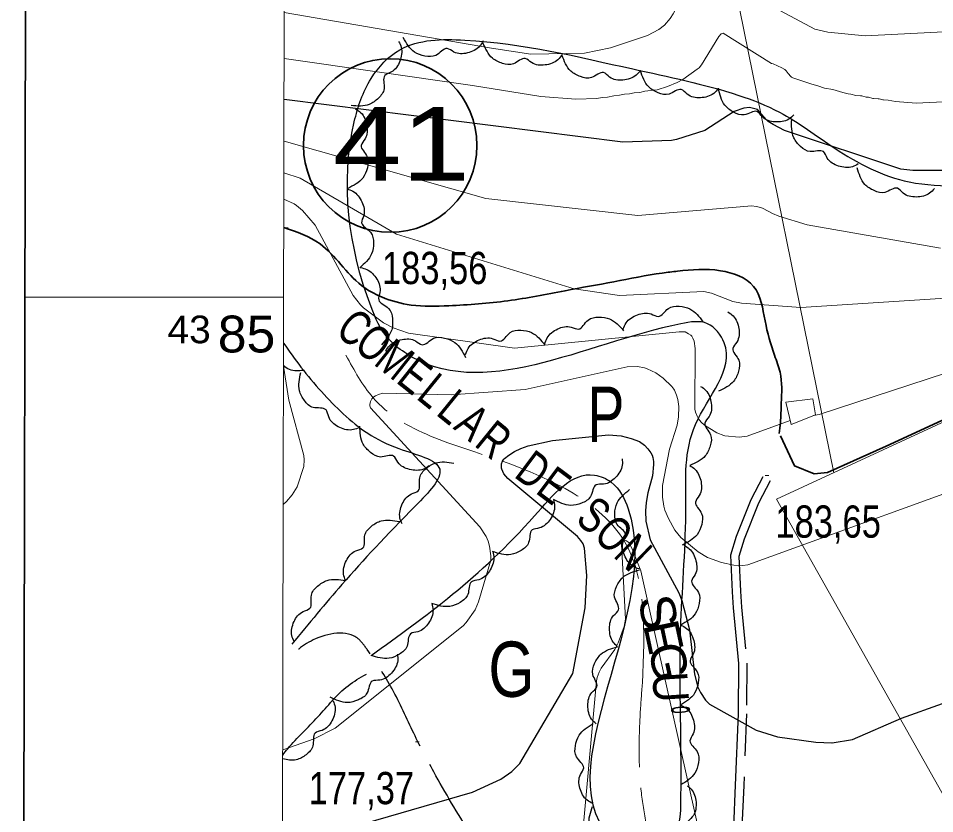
# Model space of a CAD drawing. Extents: x 483847 to 488453, y 4383581 to 4386795.
# Drawn here: x 484030.4 to 484279, y 4384859.8 to 4385075.7 of the extents above; entities that cross this region are included whole.
import ezdxf
from ezdxf.enums import TextEntityAlignment as Align

# ---------------------------------------------------------------- set-up
doc = ezdxf.new("R2010")
doc.units = 0
doc.header["$LTSCALE"] = 3.8
for name, pattern in [('DOTTED', [1.5, 0.3, -1.2]), ('LONG_DASHED', [7.5, 6, -1.5]), ('MEDIUM_DASHED', [4.5, 3, -1.5])]:
    doc.linetypes.add(name, pattern=pattern)
for name, color, linetype, lineweight in [('1', 7, 'Continuous', 13), ('13', 7, 'Continuous', 25), ('15', 7, 'LONG_DASHED', 13), ('2', 7, 'DOTTED', 13), ('27', 7, 'Continuous', 25), ('38', 7, 'Continuous', 25), ('47', 7, 'Continuous', 35), ('51', 7, 'Continuous', 13), ('6', 7, 'Continuous', 35), ('7', 7, 'Continuous', 13), ('8', 7, 'Continuous', 25), ('9', 7, 'Continuous', 13)]:
    doc.layers.add(name, color=color, linetype=linetype, lineweight=lineweight)
doc.layers.add('31', color=7, linetype='Continuous')
doc.layers.add('5', color=7, linetype='Continuous')

msp = doc.modelspace()

# ---------------------------------------------------------------- linework, layer by layer
at = {"layer": '1'}
msp.add_line((484102.37, 4385000), (484032.14, 4385000), dxfattribs=at)
at = {"layer": '1', "lineweight": 35}
msp.add_lwpolyline([(484035.03, 4386519.58), (487752.53, 4386512.52), (487747.86, 4384057.52), (484030.36, 4384064.59)], close=True, dxfattribs=at)
at = {"layer": '1'}
msp.add_lwpolyline([(484105.5, 4386448.1), (487681.9, 4386441.2), (487678, 4384129), (484100.5, 4384135.8)], close=True, dxfattribs=at)
at = {"layer": '15'}
for points in [[(484199.72, 4384895.26), (484194.73, 4384933.86), (484161.74, 4384955.47), (484126.6, 4384972.74), (484119.28, 4384984.24)], [(484199.72, 4384895.26), (484199.12, 4384887.01), (484198.9, 4384873.03), (484199.36, 4384866), (484200.74, 4384856.93), (484201.27, 4384852.68), (484201.35, 4384844.63)]]:
    msp.add_spline(points, degree=3, dxfattribs=at)
at = {"layer": '27'}
for points in [[(484126.09, 4384902.79), (484170.42, 4384940.62), (484186.72, 4384951.71), (484191.28, 4384949.75), (484195.85, 4384942.58), (484195.2, 4384850.61), (484198.46, 4384849.31), (484203.02, 4384849.96), (484206.93, 4384851.91), (484210.19, 4384864.31), (484210.19, 4384911.92), (484211.5, 4384943.23), (484214.1, 4384965.41), (484221.93, 4384987.58), (484217.36, 4384992.8), (484210.19, 4384992.8), (484135.22, 4384984.97), (484130.65, 4384988.89), (484126.09, 4384997.37), (484121.53, 4385047.59), (484126.09, 4385059.33), (484133.91, 4385067.16), (484151.52, 4385069.77), (484197.15, 4385061.94), (484225.84, 4385054.77), (484236.92, 4385050.2), (484251.92, 4385040.42), (484272.13, 4385031.28), (484285.82, 4385029.98), (484298.2, 4385029.33), (484332.11, 4385039.76), (484352.32, 4385052.16), (484358.18, 4385050.2), (484379.05, 4385045.63), (484396, 4385044.98), (484413.6, 4385057.38), (484413.6, 4385076.29), (484415.56, 4385110.21), (484421.42, 4385117.38), (484434.46, 4385125.86), (484452.06, 4385127.17), (484517.26, 4385131.08), (484535.51, 4385145.43), (484539.43, 4385153.26), (484534.21, 4385163.04), (484527.69, 4385172.17), (484530.3, 4385183.26), (484560.29, 4385234.79), (484583.76, 4385251.75), (484588.32, 4385252.4), (484664.6, 4385247.83), (484699.15, 4385252.4), (484722.1, 4385262.06)], [(484133.56, 4385069.43), (484134.25, 4385067.79), (484133.87, 4385064.02), (484131.59, 4385061.12), (484129.79, 4385060.14), (484129.61, 4385056.59), (484128.08, 4385054.02), (484125.6, 4385052.3), (484120.65, 4385051.99)], [(484156.51, 4385069.57), (484155.55, 4385068.08), (484152.22, 4385066.27), (484148.54, 4385066.53), (484146.71, 4385067.47), (484143.68, 4385065.62), (484140.7, 4385065.44), (484137.88, 4385066.53), (484134.83, 4385070.44)], [(484177.91, 4385065.83), (484176.8, 4385064.45), (484173.29, 4385063.01), (484169.65, 4385063.66), (484167.94, 4385064.8), (484164.72, 4385063.29), (484161.74, 4385063.43), (484159.06, 4385064.82), (484156.45, 4385069.04)], [(484199.18, 4385061.55), (484198.01, 4385060.22), (484194.44, 4385058.93), (484190.83, 4385059.74), (484189.17, 4385060.95), (484185.89, 4385059.58), (484182.92, 4385059.85), (484180.3, 4385061.36), (484177.88, 4385065.69)], [(484220.29, 4385056.57), (484219.07, 4385055.29), (484215.46, 4385054.13), (484211.89, 4385055.07), (484210.27, 4385056.34), (484206.94, 4385055.09), (484203.98, 4385055.47), (484201.42, 4385057.07), (484199.16, 4385061.48)], [(484240.79, 4385049.44), (484239.43, 4385048.3), (484235.7, 4385047.57), (484232.27, 4385048.91), (484230.81, 4385050.35), (484227.36, 4385049.49), (484224.46, 4385050.21), (484222.09, 4385052.09), (484220.35, 4385056.74)], [(484121.88, 4385051.1), (484123.31, 4385050.06), (484124.92, 4385046.63), (484124.45, 4385042.96), (484123.4, 4385041.2), (484125.07, 4385038.06), (484125.08, 4385035.07), (484123.83, 4385032.32), (484119.74, 4385029.51)], [(484258.29, 4385036.18), (484256.7, 4385035.4), (484252.91, 4385035.59), (484249.9, 4385037.73), (484248.83, 4385039.49), (484245.27, 4385039.49), (484242.64, 4385040.88), (484240.8, 4385043.28), (484240.23, 4385048.21)], [(484278.94, 4385029.45), (484277.67, 4385028.2), (484274.02, 4385027.18), (484270.48, 4385028.24), (484268.91, 4385029.57), (484265.54, 4385028.44), (484262.6, 4385028.92), (484260.09, 4385030.61), (484257.99, 4385035.1)], [(484119.5, 4385029.37), (484121.16, 4385028.73), (484123.6, 4385025.83), (484124.09, 4385022.17), (484123.53, 4385020.2), (484125.96, 4385017.6), (484126.74, 4385014.71), (484126.23, 4385011.73), (484123.01, 4385007.96)], [(484123.21, 4385008.01), (484124.92, 4385007.54), (484127.64, 4385004.9), (484128.5, 4385001.31), (484128.15, 4384999.29), (484130.82, 4384996.95), (484131.89, 4384994.16), (484131.69, 4384991.14), (484128.87, 4384987.06)], [(484194.54, 4384991.39), (484195.3, 4384993), (484198.37, 4384995.22), (484202.06, 4384995.44), (484203.99, 4384994.74), (484206.76, 4384996.97), (484209.69, 4384997.53), (484212.63, 4384996.81), (484216.15, 4384993.33)], [(484173.22, 4384987.26), (484173.85, 4384988.92), (484176.74, 4384991.38), (484180.4, 4384991.89), (484182.38, 4384991.34), (484184.96, 4384993.78), (484187.84, 4384994.58), (484190.83, 4384994.09), (484194.62, 4384990.89)], [(484222.93, 4384996.02), (484224.34, 4384994.94), (484225.88, 4384991.48), (484225.34, 4384987.83), (484224.26, 4384986.08), (484225.87, 4384982.91), (484225.82, 4384979.93), (484224.51, 4384977.2), (484220.37, 4384974.47)], [(484151.72, 4384984.48), (484152.43, 4384986.1), (484155.45, 4384988.41), (484159.13, 4384988.72), (484161.07, 4384988.07), (484163.79, 4384990.37), (484166.7, 4384991.01), (484169.66, 4384990.37), (484173.27, 4384986.97)], [(484102.34, 4384987.5), (484107.05, 4384981.01), (484118.55, 4384968.34), (484133.64, 4384958.91), (484144.7, 4384953.31), (484138.24, 4384943.46), (484118.16, 4384922.01), (484104.59, 4384905.83)], [(484130.07, 4384985.37), (484131.09, 4384986.83), (484134.49, 4384988.51), (484138.16, 4384988.11), (484139.94, 4384987.1), (484143.05, 4384988.83), (484146.03, 4384988.9), (484148.81, 4384987.7), (484151.7, 4384983.67)], [(484107.65, 4384980.14), (484105.89, 4384979.98), (484102.4, 4384981.48), (484102.33, 4384981.59)], [(484122.57, 4384964.44), (484120.85, 4384963.97), (484117.16, 4384964.85), (484114.59, 4384967.5), (484113.87, 4384969.42), (484110.37, 4384970.07), (484108.03, 4384971.92), (484106.66, 4384974.62), (484107.01, 4384979.57)], [(484215.52, 4384975.8), (484216.92, 4384974.71), (484218.4, 4384971.21), (484217.79, 4384967.57), (484216.67, 4384965.85), (484218.22, 4384962.65), (484218.12, 4384959.66), (484216.76, 4384956.96), (484212.57, 4384954.31)], [(484141.87, 4384954.2), (484140.33, 4384953.32), (484136.53, 4384953.25), (484133.39, 4384955.18), (484132.2, 4384956.86), (484128.66, 4384956.62), (484125.93, 4384957.84), (484123.94, 4384960.11), (484123.04, 4384964.99)], [(484134.5, 4384938.45), (484133.92, 4384940.13), (484134.55, 4384943.87), (484137.02, 4384946.61), (484138.89, 4384947.46), (484139.3, 4384951), (484140.99, 4384953.45), (484143.59, 4384955), (484148.55, 4384954.99)], [(484194.23, 4384956.16), (484194.24, 4384954.39), (484192.42, 4384951.06), (484189.19, 4384949.27), (484187.15, 4384949.07), (484185.61, 4384945.86), (484183.21, 4384944.09), (484180.25, 4384943.48), (484175.56, 4384945.1)], [(484212.58, 4384954.32), (484214.02, 4384953.27), (484215.63, 4384949.84), (484215.16, 4384946.18), (484214.12, 4384944.41), (484215.79, 4384941.27), (484215.8, 4384938.29), (484214.55, 4384935.54), (484210.47, 4384932.72)], [(484198.8, 4384926.25), (484197.17, 4384926.96), (484194.86, 4384929.97), (484194.53, 4384933.64), (484195.17, 4384935.6), (484192.86, 4384938.3), (484192.21, 4384941.21), (484192.84, 4384944.17), (484196.23, 4384947.8)], [(484175.59, 4384945.03), (484175.9, 4384943.28), (484174.68, 4384939.69), (484171.8, 4384937.38), (484169.82, 4384936.83), (484168.84, 4384933.41), (484166.78, 4384931.26), (484163.97, 4384930.14), (484159.07, 4384930.95)], [(484119.15, 4384923.1), (484118.63, 4384924.79), (484119.4, 4384928.51), (484121.97, 4384931.16), (484123.87, 4384931.94), (484124.42, 4384935.46), (484126.2, 4384937.85), (484128.85, 4384939.3), (484133.81, 4384939.1)], [(484210.95, 4384932.69), (484212.44, 4384931.74), (484214.26, 4384928.41), (484214.02, 4384924.72), (484213.08, 4384922.9), (484214.94, 4384919.87), (484215.13, 4384916.89), (484214.05, 4384914.07), (484210.15, 4384911.01)], [(484159.09, 4384930.95), (484159.4, 4384929.2), (484158.18, 4384925.61), (484155.3, 4384923.3), (484153.32, 4384922.75), (484152.35, 4384919.33), (484150.28, 4384917.18), (484147.47, 4384916.07), (484142.57, 4384916.87)], [(484192.99, 4384905.13), (484191.77, 4384906.41), (484190.79, 4384910.08), (484191.91, 4384913.6), (484193.26, 4384915.15), (484192.18, 4384918.54), (484192.71, 4384921.47), (484194.43, 4384923.96), (484198.96, 4384925.99)], [(484105.17, 4384906.52), (484104.57, 4384908.19), (484105.18, 4384911.94), (484107.64, 4384914.69), (484109.5, 4384915.56), (484109.89, 4384919.09), (484111.57, 4384921.56), (484114.16, 4384923.12), (484119.12, 4384923.14)], [(484142.59, 4384916.87), (484142.9, 4384915.12), (484141.68, 4384911.53), (484138.8, 4384909.22), (484136.82, 4384908.67), (484135.85, 4384905.25), (484133.78, 4384903.1), (484130.97, 4384901.99), (484126.08, 4384902.79)], [(484210.19, 4384911.02), (484211.71, 4384910.11), (484213.64, 4384906.84), (484213.51, 4384903.15), (484212.64, 4384901.3), (484214.59, 4384898.33), (484214.88, 4384895.36), (484213.89, 4384892.5), (484210.09, 4384889.32)], [(484187.14, 4384884.24), (484185.91, 4384885.52), (484184.92, 4384889.18), (484186.01, 4384892.7), (484187.35, 4384894.26), (484186.24, 4384897.64), (484186.75, 4384900.58), (484188.46, 4384903.08), (484192.97, 4384905.15)], [(484133.25, 4384903.13), (484133.31, 4384901.35), (484131.61, 4384897.96), (484128.44, 4384896.07), (484126.41, 4384895.8), (484124.97, 4384892.55), (484122.63, 4384890.7), (484119.69, 4384889.98), (484114.96, 4384891.45)], [(484102.1, 4384875.72), (484103.49, 4384877.45), (484111.64, 4384886.07), (484119.84, 4384894.56), (484124.8, 4384897.73)], [(484115.81, 4384890.44), (484116.3, 4384888.74), (484115.45, 4384885.04), (484112.82, 4384882.44), (484110.91, 4384881.7), (484110.29, 4384878.2), (484108.46, 4384875.84), (484105.78, 4384874.45), (484102.1, 4384874.67)], [(484210.09, 4384889.33), (484211.62, 4384888.43), (484213.57, 4384885.18), (484213.48, 4384881.49), (484212.62, 4384879.63), (484214.6, 4384876.67), (484214.91, 4384873.71), (484213.94, 4384870.84), (484210.17, 4384867.63)], [(484186.23, 4384862.58), (484184.7, 4384863.49), (484182.77, 4384866.76), (484182.9, 4384870.45), (484183.78, 4384872.3), (484181.82, 4384875.27), (484181.54, 4384878.24), (484182.53, 4384881.1), (484186.33, 4384884.28)], [(484211.99, 4384867.38), (484213.24, 4384866.12), (484214.29, 4384862.48), (484213.26, 4384858.94), (484211.94, 4384857.36), (484213.1, 4384853.99), (484212.64, 4384851.04), (484210.97, 4384848.53), (484206.5, 4384846.39)], [(484199.8, 4384844.9), (484198.05, 4384844.64), (484194.49, 4384845.96), (484192.26, 4384848.9), (484191.77, 4384850.9), (484188.38, 4384851.96), (484186.28, 4384854.09), (484185.25, 4384856.93), (484186.19, 4384861.8)]]:
    msp.add_spline(points, degree=3, dxfattribs=at)
at = {"layer": '38'}
msp.add_lwpolyline([(484232.37, 4384951.26), (484229.11, 4384945.01), (484225.2, 4384935.05), (484223.59, 4384929.97), (484224.04, 4384920.04), (484224.35, 4384915.71), (484225.8, 4384900.59), (484225.69, 4384886.94), (484224.92, 4384867.54), (484224.42, 4384856.15), (484224.68, 4384845.1), (484224.82, 4384838.89)], dxfattribs=at)
at = {"layer": '38', "linetype": 'MEDIUM_DASHED'}
msp.add_lwpolyline([(484234.41, 4384950.2), (484231.21, 4384944.06), (484227.37, 4384934.28), (484225.91, 4384929.66), (484226.34, 4384920.17), (484226.64, 4384915.9), (484228.1, 4384900.69), (484227.99, 4384886.88), (484227.22, 4384867.44), (484226.72, 4384856.13), (484226.98, 4384845.16), (484227.11, 4384840.12), (484228.41, 4384831.83), (484231.07, 4384826.18), (484235.47, 4384819.42), (484241.07, 4384813.28), (484248.65, 4384809.22), (484259.62, 4384805.88), (484266.87, 4384803.45), (484274.28, 4384801.68), (484274.48, 4384800.94), (484276.3, 4384800.79)], dxfattribs=at)
at = {"layer": '38', "linetype": 'LONG_DASHED'}
msp.add_spline([(484169.87, 4384830.1), (484162.41, 4384840.66), (484153.05, 4384854.45), (484143.1, 4384871.17), (484137.33, 4384882.34), (484131.36, 4384894.47), (484125.03, 4384904.34), (484122.56, 4384907.32), (484110.41, 4384907), (484102.15, 4384900.59)], degree=3, dxfattribs=at)
at = {"layer": '47', "lineweight": 13}
msp.add_lwpolyline([(484240.11, 4384965.43), (484238.62, 4384971.48), (484245.97, 4384972.4), (484246.73, 4384968.08)], close=True, dxfattribs=at)
at = {"layer": '51'}
for points in [[(484196.34, 4385204.9), (484210.08, 4385148.51), (484225, 4385083.74), (484251.62, 4384952.33)], [(484484.3, 4385057.04), (484379.62, 4385011.61), (484236.15, 4384945.17), (484295.85, 4384839.28)]]:
    msp.add_lwpolyline(points, dxfattribs=at)
at = {"layer": '6'}
msp.add_lwpolyline([(484459.08, 4385019.18), (484455.39, 4385016.01), (484448.82, 4385016.01), (484436.64, 4385020.7), (484429.76, 4385025.69), (484424.76, 4385032.25), (484421.64, 4385032.25), (484282.12, 4384967.05), (484265.88, 4384959.56), (484249.94, 4384952.38), (484246.29, 4384952.07), (484240.98, 4384954.25), (484237.23, 4384962.37)], dxfattribs=at)
msp.add_circle((484131.28, 4385041.16), 23.55, dxfattribs=at)
msp.add_spline([(484102.41, 4385018.95), (484112.24, 4385014.43), (484123.49, 4385003.19), (484128.93, 4385000.06), (484136.94, 4384997.86), (484147.17, 4384997.68), (484163.2, 4384999.01), (484178.72, 4385001.76), (484191.97, 4385004.19), (484205.12, 4385006.55), (484209.27, 4385007.05), (484220.87, 4385007.19), (484229.91, 4385002.93), (484233.01, 4384993.54), (484235.57, 4384984.24), (484237.09, 4384979.61), (484237.41, 4384971.23), (484237.15, 4384965.97), (484236.81, 4384962.99)], degree=3, dxfattribs=at)
at = {"layer": '7'}
for p, q in [((484102.6, 4385018.8), (484103.6, 4385018.8)), ((484233.06, 4384951.61), (484234.06, 4384951.61)), ((484138.1, 4384879.34), (484139.1, 4384879.34))]:
    msp.add_line(p, q, dxfattribs=at)
at = {"layer": '8'}
for points in [[(484286.97, 4385034.4), (484273.13, 4385034.35), (484269.81, 4385034.71), (484238.31, 4385045.23), (484235.18, 4385046.83), (484233.86, 4385047.7), (484233.26, 4385048.18), (484230.91, 4385050.9), (484228.76, 4385051.47), (484227.27, 4385051.28), (484224.6, 4385050.4), (484216.64, 4385045.24), (484208.93, 4385042.78), (484207.59, 4385042.5), (484194.43, 4385042.03), (484102.48, 4385053.67)], [(484117.72, 4384855.23), (484153.62, 4384865.67), (484161.3, 4384869.17), (484164.25, 4384871.24), (484166.41, 4384873.48), (484180.86, 4384897.88), (484184.19, 4384915.69), (484184.63, 4384924.5), (484184.01, 4384931.89), (484183.62, 4384933.03), (484182.98, 4384933.97), (484182.06, 4384935.04), (484163.2, 4384950.75), (484162.07, 4384952.1), (484161.59, 4384953.33), (484161.52, 4384953.62), (484161.46, 4384954.13), (484161.46, 4384954.79), (484161.74, 4384955.47), (484162.13, 4384956.04), (484162.3, 4384956.22), (484163.44, 4384957.14), (484164.98, 4384958.15), (484166.69, 4384958.95), (484166.7, 4384958.95), (484166.71, 4384958.96), (484168.71, 4384959.62), (484175.33, 4384961.13), (484190.5, 4384962.68), (484193.93, 4384962.33), (484196.68, 4384961.65), (484198.92, 4384960.82), (484200.27, 4384959.84), (484201.23, 4384958.82), (484202.03, 4384957.71), (484202.33, 4384957.08), (484202.52, 4384956.46), (484202.72, 4384955.42), (484202.76, 4384954.63), (484202.47, 4384951.55), (484201.2, 4384946.86), (484200.7, 4384944.29), (484200.56, 4384942.03), (484200.69, 4384939.25), (484201.86, 4384934.11), (484209.56, 4384919.78), (484210.38, 4384917.66), (484212.49, 4384909.71), (484213.85, 4384897.65), (484214.72, 4384894.15), (484215.44, 4384892.69), (484216.88, 4384890.65), (484217.95, 4384889.54), (484230.56, 4384882.48), (484236.37, 4384880.65), (484246.75, 4384879.22), (484251.16, 4384879.03), (484251.18, 4384879.04), (484251.19, 4384879.04), (484251.21, 4384879.05), (484256.75, 4384879.99), (484270.06, 4384885.77), (484281.11, 4384889.71)]]:
    msp.add_lwpolyline(points, dxfattribs=at)
at = {"layer": '9'}
for points in [[(484102.54, 4385077.28), (484158.8, 4385067.57), (484169.44, 4385065.99), (484184.02, 4385066.23), (484191.09, 4385067.67), (484201.13, 4385070.97), (484204.17, 4385072.64), (484205.68, 4385073.86), (484207.26, 4385075.67), (484208.05, 4385076.89), (484211.33, 4385083.3), (484211.98, 4385084.27), (484212.54, 4385084.86), (484212.97, 4385085.21), (484213.73, 4385085.71), (484214.54, 4385086.08), (484216.89, 4385086.72), (484218.66, 4385086.69), (484219.89, 4385086.51), (484222.49, 4385085.66), (484246.54, 4385072.76), (484250.01, 4385071.93), (484260.21, 4385070.91), (484306.34, 4385073.29)], [(484246.15, 4384967.85), (484247.65, 4384968.12), (484438.96, 4385030.72), (484442.78, 4385032.54), (484453.15, 4385039.21), (484455.46, 4385040.7), (484465.61, 4385045.22), (484470.29, 4385046.25), (484494, 4385053.14), (484497.33, 4385054.72), (484508.86, 4385063.24), (484509.55, 4385063.96), (484510.43, 4385065.35), (484511.21, 4385067.08), (484511.22, 4385067.1), (484511.22, 4385067.16), (484511.8, 4385069.58), (484511.9, 4385074.36)], [(484102.51, 4385064.79), (484153.58, 4385057.42), (484172.15, 4385054.42), (484181.62, 4385053.72), (484187.36, 4385053.96), (484188.79, 4385054.18), (484190.25, 4385054.3), (484192, 4385054.67), (484193.52, 4385054.83), (484194.82, 4385055.08), (484196.21, 4385055.19), (484197.44, 4385055.42), (484198.98, 4385055.55), (484200.37, 4385055.89), (484203.72, 4385056.28), (484206.52, 4385057.14), (484209.16, 4385058.27), (484210.7, 4385059.07), (484214.59, 4385061.88), (484215.08, 4385062.22), (484215.75, 4385063.06), (484220.5, 4385070.71), (484221.12, 4385071.47), (484221.37, 4385071.55), (484221.67, 4385071.61), (484234.77, 4385063.4), (484235.19, 4385063.28), (484237.53, 4385062.26), (484238.34, 4385061.8), (484238.72, 4385061.45), (484239.28, 4385060.67), (484239.96, 4385059.88), (484240.22, 4385059.7), (484240.52, 4385059.53), (484245.67, 4385057.77), (484247.28, 4385057.34), (484249.1, 4385056.71), (484251.35, 4385056.32), (484254.12, 4385055.51), (484254.85, 4385055.4), (484255.53, 4385055.22), (484256.3, 4385055.13), (484257.66, 4385054.77), (484258.94, 4385054.68), (484259.24, 4385054.64), (484260.42, 4385054.31), (484261.08, 4385054.26), (484262.26, 4385053.95), (484262.41, 4385053.93), (484263.68, 4385053.87)], [(484263.68, 4385053.87), (484263.97, 4385053.83), (484264.98, 4385053.57), (484265.12, 4385053.54), (484266.44, 4385053.47), (484268.36, 4385053.1), (484273.97, 4385052.67), (484286.84, 4385053.27)], [(484280.58, 4385013.34), (484244.45, 4385019.59), (484236.7, 4385021.97), (484234.99, 4385022.73), (484232.53, 4385024.03), (484231.85, 4385024.3), (484230.57, 4385024.61), (484229.45, 4385024.77), (484198.47, 4385022.19), (484157.26, 4385026.74), (484102.46, 4385042.34)], [(484289.05, 4385000.17), (484242.69, 4384997.21), (484226.61, 4384998.39), (484224.3, 4384998.85), (484218.5, 4385001.1), (484216.38, 4385001.58), (484193.51, 4385000.48), (484181.23, 4385002.27), (484133, 4385017.09), (484106.82, 4385032.26), (484102.44, 4385033.78)], [(484102.43, 4385026.56), (484105.24, 4385025.31), (484105.88, 4385024.86), (484107.46, 4385023.51), (484110.9, 4385019.56), (484121.25, 4385000.47), (484123.23, 4384997.88), (484124.06, 4384997.11), (484129.47, 4384993.03), (484132.12, 4384991.69), (484136.24, 4384990.25), (484164.98, 4384986.17), (484209.67, 4384990.59), (484211.28, 4384990.57), (484212.2, 4384990.09), (484212.82, 4384989.68), (484213.09, 4384989.41), (484213.43, 4384988.86), (484213.77, 4384988.08), (484213.79, 4384988.05), (484214.06, 4384986.03), (484213.93, 4384969.57), (484214.11, 4384968.81), (484214.55, 4384967.7), (484214.93, 4384967.02), (484215.65, 4384966.05), (484216.59, 4384965.22), (484219.88, 4384963.15), (484221.8, 4384962.49), (484221.85, 4384962.46), (484222.12, 4384962.41), (484226.02, 4384962.05), (484228.18, 4384962.31), (484239.83, 4384966.57)], [(484217.41, 4384929.38), (484214.85, 4384930.9), (484210.11, 4384934.82), (484208.51, 4384936.73), (484206.78, 4384939.89), (484205.83, 4384942.17), (484205.52, 4384943.25), (484205.18, 4384945.69), (484205.19, 4384948.89), (484207.06, 4384958.76), (484209.11, 4384965.23), (484209.54, 4384967.55), (484209.6, 4384970.33), (484209.33, 4384972.26), (484208.99, 4384973.43), (484208.4, 4384974.75), (484208.26, 4384974.99), (484207.72, 4384975.76), (484205.35, 4384978.05), (484203.37, 4384979.46), (484201.03, 4384980.59), (484200.28, 4384980.84), (484198.36, 4384981.14), (484195.56, 4384981.07), (484167.89, 4384974.92), (484147.78, 4384973.5), (484129.24, 4384973.91), (484128.11, 4384973.58), (484127.32, 4384973.23), (484126.6, 4384972.74), (484126.44, 4384972.58), (484126.3, 4384972.4), (484125.93, 4384971.65), (484125.77, 4384970.89), (484125.77, 4384970.53), (484125.93, 4384970.01), (484155.56, 4384937.71), (484157.28, 4384935.01), (484157.82, 4384933.8), (484158.23, 4384932.38), (484158.56, 4384929.83), (484158.55, 4384928.63), (484155.28, 4384917.32), (484154.29, 4384915.17), (484151.9, 4384911.74), (484151.12, 4384910.82), (484116.35, 4384883.02), (484110.61, 4384880.12), (484102.1, 4384877.17)], [(484102.25, 4384943.76), (484103.11, 4384944.53), (484104.69, 4384946.38), (484106, 4384948.5), (484107.87, 4384954.07), (484107.93, 4384955.86), (484107.83, 4384957.05), (484103.77, 4384972.01), (484102.33, 4384981.23), (484102.33, 4384981.24), (484102.33, 4384981.25), (484102.33, 4384981.26), (484102.33, 4384981.27), (484102.33, 4384981.28), (484102.33, 4384981.29), (484102.33, 4384981.3), (484102.33, 4384981.31), (484102.33, 4384981.32), (484102.33, 4384981.33), (484102.33, 4384981.34), (484102.33, 4384981.35), (484102.33, 4384981.36)], [(484376.13, 4384980.87), (484228.37, 4384927.37), (484226.96, 4384927.2), (484224.57, 4384927.27), (484221.15, 4384927.96), (484217.41, 4384929.38)], [(484182.94, 4384848.02), (484187.22, 4384895.88), (484187.42, 4384896.75), (484187.96, 4384898.24), (484188.53, 4384899.32), (484192.22, 4384904.35), (484193.18, 4384906.15), (484194.81, 4384910.58), (484195.14, 4384912.61), (484194.04, 4384932.95), (484194.17, 4384933.39), (484194.24, 4384933.49), (484194.32, 4384933.58), (484194.73, 4384933.86), (484195.23, 4384933.92), (484195.38, 4384933.89), (484195.52, 4384933.82), (484196.04, 4384933.39), (484196.86, 4384931.86), (484199.29, 4384925.76), (484216.29, 4384849.52)]]:
    msp.add_lwpolyline(points, dxfattribs=at)

# ---------------------------------------------------------------- texts
at = {"layer": '13', "width": 1.25}
msp.add_text('41', height=20, dxfattribs=at).set_placement((484134.34, 4385031.62), align=Align.CENTER)
at = {"layer": '2', "width": 1.05}
for s, height, p in [('43', 7.5, (484082.57, 4384987.5)), ('85', 10, (484100.1, 4384985))]:
    msp.add_text(s, height=height, dxfattribs=at).set_placement(p, align=Align.RIGHT)
at = {"layer": '31'}
for s, width, p in [('P', 0.75, (484189.82, 4384960.73)), ('G', 0.8, (484164.17, 4384891.53))]:
    msp.add_text(s, height=15, dxfattribs=dict(at, width=width)).set_placement(p, align=Align.CENTER)
at = {"layer": '5'}
for s, rotation, width, p in [('C', 321.525, 0.75, (484118.72, 4384988.04)), ('O', 321.525, 0.75, (484123.96, 4384983.87)), ('M', 321.525, 0.75, (484129.58, 4384979.4)), ('E', 321.525, 0.75, (484135.05, 4384975.05)), ('L', 320.899, 0.75, (484140.12, 4384970.95)), ('L', 320.899, 0.75, (484145.47, 4384966.59)), ('A', 320.899, 0.75, (484150.6, 4384962.42)), ('R', 320.899, 0.75, (484156.47, 4384957.65)), ('D', 323.31, 0.75, (484167.33, 4384949.32)), ('E', 323.31, 0.75, (484172.95, 4384945.12)), ('S', 323.31, 0.75, (484183.78, 4384937.06)), ('O', 316.165, 0.75, (484188.77, 4384932.36)), ('N', 316.165, 0.75, (484194.03, 4384927.32)), ('S', 281.991, 1.1, (484199.39, 4384913.58)), ('E', 281.991, 1.05, (484200.81, 4384906.84)), ('G', 281.991, 1.05, (484202.24, 4384900.09)), ('U', 273.819, 0.9, (484202.65, 4384893.85)), ('º', 273.819, 0.4, (484203.07, 4384887.56))]:
    msp.add_text(s, height=9.49, rotation=rotation, dxfattribs=dict(at, width=width)).set_placement(p, align=Align.CENTER)
at = {"layer": '7', "width": 0.8}
for s, p in [('183,56', (484129.03, 4385003.55)), ('183,65', (484235.81, 4384934.73)), ('177,37', (484109.13, 4384862.4))]:
    msp.add_text(s, height=8.75, dxfattribs=at).set_placement(p)

doc.saveas('drawing.dxf')
